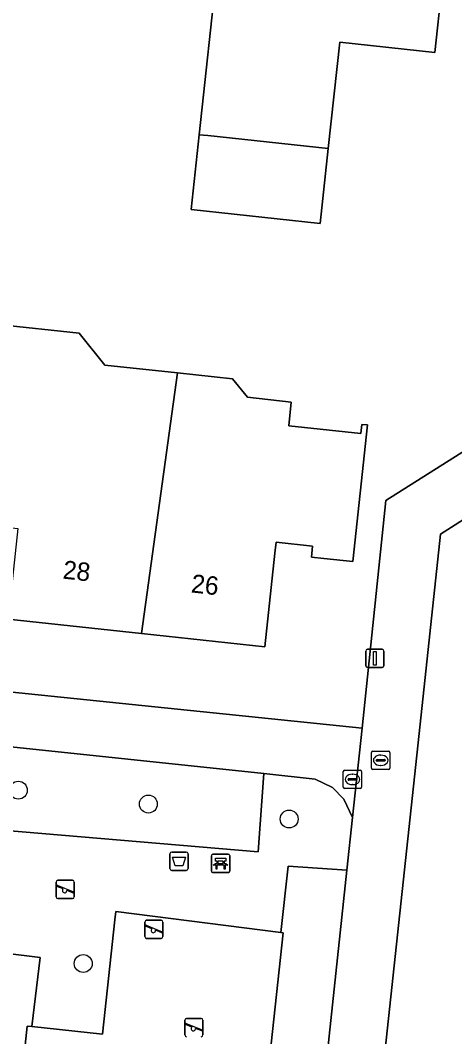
# Model space of a CAD drawing. Extents: x 162156 to 163172, y 378995 to 380779.
# Drawn here: x 162471.9 to 162495.6, y 380530.2 to 380585.7 of the extents above; entities that cross this region are included whole.
import ezdxf

# ---------------------------------------------------------------- set-up
doc = ezdxf.new("R2010")
doc.units = 0
for name, color, linetype in [('IMGEO_Afvalbak', 7, 'Continuous'), ('IMGEO_Bank', 7, 'Continuous'), ('IMGEO_Boom', 7, 'Continuous'), ('IMGEO_Erf', 7, 'Continuous'), ('IMGEO_Groenvoorziening', 7, 'Continuous'), ('IMGEO_Kolk', 7, 'Continuous'), ('IMGEO_Lichtmast', 7, 'Continuous'), ('IMGEO_Pand', 7, 'Continuous'), ('IMGEO_Pand_nummerreeks', 7, 'Continuous'), ('IMGEO_Rioolput', 7, 'Continuous'), ('IMGEO_Speelvoorziening', 7, 'Continuous'), ('IMGEO_Terreindeel_zand', 7, 'Continuous'), ('IMGEO_Voetpad_open', 7, 'Continuous')]:
    doc.layers.add(name, color=color, linetype=linetype)

msp = doc.modelspace()

# ---------------------------------------------------------------- linework, layer by layer
at = {"layer": 'IMGEO_Afvalbak'}
for p, q in [((162480.081, 380539.399), (162480.081, 380540.199)), ((162480.081, 380540.199), (162480.081, 380539.399)), ((162480.181, 380540.299), (162480.971, 380540.299)), ((162480.971, 380540.299), (162480.181, 380540.299)), ((162481.071, 380540.199), (162481.071, 380539.399)), ((162481.071, 380539.399), (162481.071, 380540.199)), ((162480.971, 380539.299), (162480.181, 380539.299)), ((162480.181, 380539.299), (162480.971, 380539.299))]:
    msp.add_line(p, q, dxfattribs=at)
msp.add_lwpolyline([(162480.224, 380540.013), (162480.928, 380540.013), (162480.779, 380539.543), (162480.373, 380539.543), (162480.224, 380540.013)], dxfattribs=at)
for centre, start, end in [((162480.181, 380540.199), 90, 180), ((162480.181, 380540.199), 90, 180), ((162480.971, 380540.199), 0, 90), ((162480.971, 380540.199), 360, 90), ((162480.181, 380539.399), 180, 270), ((162480.181, 380539.399), 180, 270), ((162480.971, 380539.399), 270, 0), ((162480.971, 380539.399), 270, 0)]:
    msp.add_arc(centre, 0.1, start, end, dxfattribs=at)
at = {"layer": 'IMGEO_Bank'}
for p, q in [((162482.342, 380539.255), (162482.342, 380540.096)), ((162482.342, 380540.096), (162482.342, 380539.255)), ((162482.417, 380540.18), (162483.258, 380540.18)), ((162483.258, 380540.18), (162482.417, 380540.18)), ((162483.342, 380540.105), (162483.342, 380539.264)), ((162483.342, 380539.264), (162483.342, 380540.105)), ((162483.039, 380539.578), (162482.646, 380539.578)), ((162482.651, 380539.686), (162482.651, 380539.792)), ((162482.695, 380539.792), (162482.695, 380539.686)), ((162482.983, 380539.798), (162482.701, 380539.798)), ((162482.701, 380539.68), (162482.983, 380539.68)), ((162482.989, 380539.686), (162482.989, 380539.792)), ((162483.033, 380539.792), (162483.033, 380539.686)), ((162483.267, 380539.18), (162482.426, 380539.18)), ((162482.426, 380539.18), (162483.267, 380539.18))]:
    msp.add_line(p, q, dxfattribs=at)
for points in [[(162482.589, 380539.578), (162482.447, 380539.578), (162482.559, 380539.68), (162482.645, 380539.68)], [(162482.645, 380539.798), (162482.559, 380539.798), (162482.559, 380539.959), (162483.122, 380539.959), (162483.122, 380539.798), (162483.039, 380539.798)], [(162482.639, 380539.571), (162482.639, 380539.364), (162482.596, 380539.364), (162482.596, 380539.571)], [(162483.039, 380539.68), (162483.122, 380539.68), (162483.234, 380539.578), (162483.095, 380539.578)], [(162483.089, 380539.571), (162483.089, 380539.364), (162483.045, 380539.364), (162483.045, 380539.571)]]:
    msp.add_lwpolyline(points, dxfattribs=at)
for centre, radius, start, end in [((162482.42, 380540.102), 0.0779, 92.4484, 184.2845), ((162482.42, 380540.102), 0.0779, 92.4484, 184.2845), ((162483.264, 380540.102), 0.0779, 2.4484, 94.2845), ((162483.264, 380540.102), 0.0779, 2.4484, 94.2845), ((162482.589, 380539.571), 0.00671, 2.8957, 87.1043), ((162482.646, 380539.571), 0.00671, 92.8957, 177.1043), ((162482.644, 380539.791), 0.00671, 2.8957, 87.1043), ((162482.644, 380539.687), 0.00671, 272.8957, 357.1043), ((162482.701, 380539.791), 0.00671, 92.8957, 177.1043), ((162482.701, 380539.687), 0.00671, 182.8957, 267.1043), ((162482.983, 380539.791), 0.00671, 2.8957, 87.1043), ((162482.983, 380539.687), 0.00671, 272.8957, 357.1043), ((162483.04, 380539.791), 0.00671, 92.8957, 177.1043), ((162483.04, 380539.687), 0.00671, 182.8957, 267.1043), ((162483.038, 380539.571), 0.00671, 2.8957, 87.1043), ((162483.095, 380539.571), 0.00671, 92.8957, 177.1043), ((162482.42, 380539.258), 0.0779, 182.4484, 274.2845), ((162482.42, 380539.258), 0.0779, 182.4484, 274.2845), ((162483.264, 380539.258), 0.0779, 272.4484, 4.2845), ((162483.264, 380539.258), 0.0779, 272.4484, 4.2845)]:
    msp.add_arc(centre, radius, start, end, dxfattribs=at)
at = {"layer": 'IMGEO_Boom'}
for centre in [(162471.814, 380543.676), (162478.904, 380542.921), (162486.581, 380542.104), (162475.353, 380534.216)]:
    msp.add_circle(centre, 0.489, dxfattribs=at)
at = {"layer": 'IMGEO_Erf'}
for points in [[(162502.189, 380600.029), (162502.472, 380602.43), (162503.344, 380607.897), (162504.412, 380614.587), (162506.479, 380624.601), (162500, 380625.199), (162474.413, 380627.947), (162438.013, 380631.313), (162439.468, 380615.71), (162440.015, 380601.307), (162439.768, 380588.845), (162437.05, 380560.078), (162436.315, 380552.915), (162465.464, 380549.639), (162490.566, 380547.063), (162491.852, 380559.491), (162500, 380564.632), (162501.13, 380565.345), (162499.992, 380567.526)], [(162470.695, 380569.092), (162475.128, 380568.614), (162476.527, 380566.876), (162480.488, 380566.449), (162483.486, 380566.126), (162484.311, 380565.121), (162486.697, 380564.863), (162486.558, 380563.571), (162490.485, 380563.147), (162490.539, 380563.644), (162490.857, 380563.61), (162490.052, 380556.153), (162488.477, 380556.323), (162487.795, 380556.397), (162487.86, 380556.996), (162485.872, 380557.211), (162485.807, 380556.611), (162485.256, 380551.504), (162478.538, 380552.228), (162471.254, 380553.014)], [(162503.119, 380562.939), (162500, 380560.947), (162494.84, 380557.651), (162493.667, 380546.763), (162491.375, 380525.475)]]:
    msp.add_lwpolyline(points, dxfattribs=at)
msp.add_lwpolyline([(162481.674, 380579.453), (162482.671, 380588.712), (162484.697, 380588.494), (162485.082, 380592.069), (162485.476, 380595.729), (162483.408, 380595.952), (162484.419, 380605.366), (162484.765, 380605.338), (162484.995, 380608.169), (162490.766, 380607.701), (162490.528, 380604.766), (162491.55, 380604.656), (162490.887, 380598.495), (162496.039, 380597.94), (162495.295, 380591.027), (162494.532, 380583.945), (162489.336, 380584.504), (162488.71, 380578.696), (162488.27, 380574.611), (162481.234, 380575.368)], close=True, dxfattribs=at)
at = {"layer": 'IMGEO_Groenvoorziening'}
for points in [[(162469.868, 380541.578), (162484.897, 380540.319), (162485.2, 380544.58), (162470.351, 380546.161)], [(162486.523, 380539.523), (162489.731, 380539.305), (162490.036, 380542.183), (162489.57, 380543.192), (162488.951, 380543.816), (162488.005, 380544.281), (162485.2, 380544.58), (162484.897, 380540.319), (162469.868, 380541.578), (162469.175, 380535.01), (162473.002, 380534.554), (162472.559, 380530.774), (162476.412, 380530.364), (162477.075, 380536.599), (162477.123, 380537.052), (162486.125, 380535.903)], [(162489.731, 380539.305), (162486.523, 380539.523), (162486.125, 380535.903), (162486.251, 380535.887), (162485.391, 380527.81), (162485.237, 380527.826), (162482.178, 380500), (162481.589, 380494.65), (162484.947, 380494.337), (162485.141, 380496.162), (162485.549, 380500)], [(162467.353, 380486.346), (162468.953, 380500), (162471.523, 380521.934), (162469.762, 380522.121), (162469.984, 380524.21), (162471.585, 380524.04), (162472.305, 380530.801), (162472.559, 380530.774), (162473.002, 380534.554), (162469.175, 380535.01), (162469.055, 380533.871), (162467.978, 380524.494), (162467.276, 380517.746), (162465.46, 380500), (162464.077, 380486.7)]]:
    msp.add_lwpolyline(points, close=True, dxfattribs=at)
at = {"layer": 'IMGEO_Kolk'}
for p, q in [((162489.533, 380543.84), (162489.533, 380544.692)), ((162489.608, 380544.766), (162490.46, 380544.766)), ((162490.021, 380544.546), (162490.046, 380544.546)), ((162490.534, 380544.692), (162490.534, 380543.84)), ((162489.792, 380544.26), (162489.792, 380544.272)), ((162490.23, 380544.223), (162489.832, 380544.223)), ((162489.835, 380544.309), (162490.233, 380544.309)), ((162490.044, 380543.986), (162490.019, 380543.986)), ((162490.276, 380544.272), (162490.276, 380544.26)), ((162490.46, 380543.766), (162489.608, 380543.766))]:
    msp.add_line(p, q, dxfattribs=at)
for points in [[(162489.533, 380543.84), (162489.533, 380544.692)], [(162489.608, 380544.766), (162490.46, 380544.766)], [(162490.534, 380544.692), (162490.534, 380543.84)], [(162490.46, 380543.766), (162489.608, 380543.766)]]:
    msp.add_lwpolyline(points, dxfattribs=at)
for centre, radius, start, end in [((162489.61, 380544.69), 0.0765, 91.552, 178.448), ((162489.61, 380544.69), 0.0765, 91.552, 178.448), ((162490.458, 380544.69), 0.0765, 1.552, 88.448), ((162490.458, 380544.69), 0.0765, 1.552, 88.448), ((162489.832, 380544.269), 0.0403, 85.8775, 175.7526), ((162489.829, 380544.259), 0.0366, 178.938, 274.7102), ((162490.233, 380544.266), 0.043, 264.8664, 352.4533), ((162490.237, 380544.271), 0.0386, 1.7309, 96.639), ((162489.61, 380543.842), 0.0765, 181.552, 268.448), ((162489.61, 380543.842), 0.0765, 181.552, 268.448), ((162490.458, 380543.842), 0.0765, 271.552, 358.448), ((162490.458, 380543.842), 0.0765, 271.552, 358.448)]:
    msp.add_arc(centre, radius, start, end, dxfattribs=at)
for centre, major_axis, ratio, start_param, end_param in [((162490.02, 380544.266), (-0.387, 0.002), 0.722429, 4.712389, 7.853982), ((162490.045, 380544.266), (-0.39, 0.002), 0.717154, 1.570796, 4.712389)]:
    msp.add_ellipse(centre, major_axis=major_axis, ratio=ratio, start_param=start_param, end_param=end_param, dxfattribs=at)
at = {"layer": 'IMGEO_Lichtmast'}
for p, q in [((162490.757, 380550.473), (162490.757, 380551.273)), ((162490.757, 380551.273), (162490.757, 380550.473)), ((162490.857, 380551.373), (162491.647, 380551.373)), ((162491.647, 380551.373), (162490.857, 380551.373)), ((162491.747, 380551.273), (162491.747, 380550.473)), ((162491.747, 380550.473), (162491.747, 380551.273)), ((162491.647, 380550.373), (162490.857, 380550.373)), ((162490.857, 380550.373), (162491.647, 380550.373))]:
    msp.add_line(p, q, dxfattribs=at)
msp.add_lwpolyline([(162491.177, 380551.248), (162491.327, 380551.248), (162491.327, 380550.498), (162491.177, 380550.498), (162491.177, 380551.248)], dxfattribs=at)
for centre, start, end in [((162490.857, 380551.273), 90, 180), ((162490.857, 380551.273), 90, 180), ((162491.647, 380551.273), 0, 90), ((162491.647, 380551.273), 360, 90), ((162490.857, 380550.473), 180, 270), ((162490.857, 380550.473), 180, 270), ((162491.647, 380550.473), 270, 0), ((162491.647, 380550.473), 270, 0)]:
    msp.add_arc(centre, 0.1, start, end, dxfattribs=at)
at = {"layer": 'IMGEO_Pand'}
for points in [[(162488.71, 380578.696), (162489.336, 380584.504), (162494.532, 380583.945), (162495.295, 380591.027), (162485.082, 380592.069), (162484.697, 380588.494), (162482.671, 380588.712), (162481.674, 380579.453), (162482.144, 380579.402)], [(162488.71, 380578.696), (162482.144, 380579.402), (162481.674, 380579.453), (162481.234, 380575.368), (162488.27, 380574.611)], [(162478.538, 380552.228), (162480.488, 380566.449), (162476.527, 380566.876), (162475.128, 380568.614), (162470.695, 380569.092), (162468.878, 380567.629), (162468.642, 380565.441), (162467.658, 380565.547), (162466.753, 380565.645), (162466.045, 380558.576), (162471.787, 380557.957), (162471.254, 380553.014)], [(162478.538, 380552.228), (162485.256, 380551.504), (162485.807, 380556.611), (162485.872, 380557.211), (162487.86, 380556.996), (162487.795, 380556.397), (162488.477, 380556.323), (162490.052, 380556.153), (162490.857, 380563.61), (162490.539, 380563.644), (162490.485, 380563.147), (162486.558, 380563.571), (162486.697, 380564.863), (162484.311, 380565.121), (162483.486, 380566.126), (162480.488, 380566.449)]]:
    msp.add_lwpolyline(points, close=True, dxfattribs=at)
at = {"layer": 'IMGEO_Rioolput'}
for p, q in [((162491.076, 380544.884), (162491.076, 380545.736)), ((162491.151, 380545.81), (162492.003, 380545.81)), ((162492.077, 380545.736), (162492.077, 380544.884)), ((162491.335, 380545.304), (162491.335, 380545.316)), ((162491.773, 380545.267), (162491.375, 380545.267)), ((162491.378, 380545.353), (162491.776, 380545.353)), ((162491.564, 380545.59), (162491.589, 380545.59)), ((162491.819, 380545.316), (162491.819, 380545.304)), ((162492.003, 380544.81), (162491.151, 380544.81)), ((162491.587, 380545.03), (162491.562, 380545.03))]:
    msp.add_line(p, q, dxfattribs=at)
for points in [[(162491.076, 380544.884), (162491.076, 380545.736)], [(162491.151, 380545.81), (162492.003, 380545.81)], [(162492.077, 380545.736), (162492.077, 380544.884)], [(162492.003, 380544.81), (162491.151, 380544.81)]]:
    msp.add_lwpolyline(points, dxfattribs=at)
for centre, radius, start, end in [((162491.153, 380545.734), 0.0765, 91.552, 178.448), ((162491.153, 380545.734), 0.0765, 91.552, 178.448), ((162492.001, 380545.734), 0.0765, 1.552, 88.448), ((162492.001, 380545.734), 0.0765, 1.552, 88.448), ((162491.375, 380545.313), 0.0403, 85.8775, 175.7526), ((162491.372, 380545.303), 0.0366, 178.938, 274.7102), ((162491.776, 380545.31), 0.043, 264.8664, 352.4533), ((162491.78, 380545.315), 0.0386, 1.7309, 96.639), ((162491.153, 380544.886), 0.0765, 181.552, 268.448), ((162491.153, 380544.886), 0.0765, 181.552, 268.448), ((162492.001, 380544.886), 0.0765, 271.552, 358.448), ((162492.001, 380544.886), 0.0765, 271.552, 358.448)]:
    msp.add_arc(centre, radius, start, end, dxfattribs=at)
for centre, major_axis, ratio, start_param, end_param in [((162491.563, 380545.31), (-0.387, 0.002), 0.722429, 4.712389, 7.853982), ((162491.588, 380545.31), (-0.39, 0.002), 0.717154, 1.570796, 4.712389)]:
    msp.add_ellipse(centre, major_axis=major_axis, ratio=ratio, start_param=start_param, end_param=end_param, dxfattribs=at)
at = {"layer": 'IMGEO_Speelvoorziening'}
for p, q in [((162473.871, 380537.86), (162473.871, 380538.66)), ((162473.871, 380538.66), (162473.871, 380537.86)), ((162474.254, 380538.288), (162473.915, 380538.425)), ((162473.94, 380538.485), (162474.816, 380538.132)), ((162473.971, 380538.76), (162474.761, 380538.76)), ((162474.761, 380538.76), (162473.971, 380538.76)), ((162474.861, 380538.66), (162474.861, 380537.86)), ((162474.861, 380537.86), (162474.861, 380538.66)), ((162474.792, 380538.072), (162474.452, 380538.209)), ((162474.761, 380537.76), (162473.971, 380537.76)), ((162473.971, 380537.76), (162474.761, 380537.76)), ((162478.711, 380535.683), (162478.711, 380536.483)), ((162478.711, 380536.483), (162478.711, 380535.683)), ((162479.094, 380536.111), (162478.755, 380536.248)), ((162478.78, 380536.308), (162479.656, 380535.955)), ((162478.811, 380536.583), (162479.601, 380536.583)), ((162479.601, 380536.583), (162478.811, 380536.583)), ((162479.701, 380536.483), (162479.701, 380535.683)), ((162479.701, 380535.683), (162479.701, 380536.483)), ((162479.632, 380535.895), (162479.292, 380536.032)), ((162479.601, 380535.583), (162478.811, 380535.583)), ((162478.811, 380535.583), (162479.601, 380535.583)), ((162480.993, 380531.224), (162481.783, 380531.224)), ((162481.783, 380531.224), (162480.993, 380531.224)), ((162480.893, 380530.324), (162480.893, 380531.124)), ((162480.893, 380531.124), (162480.893, 380530.324)), ((162481.276, 380530.752), (162480.937, 380530.889)), ((162480.962, 380530.949), (162481.838, 380530.596)), ((162481.814, 380530.536), (162481.474, 380530.673)), ((162481.883, 380531.124), (162481.883, 380530.324)), ((162481.883, 380530.324), (162481.883, 380531.124))]:
    msp.add_line(p, q, dxfattribs=at)
for centre, radius, start, end in [((162473.971, 380538.66), 0.1, 90, 180), ((162473.971, 380538.66), 0.1, 90, 180), ((162473.928, 380538.455), 0.0327, 68.078, 248.078), ((162474.761, 380538.66), 0.1, 0, 90), ((162474.761, 380538.66), 0.1, 360, 90), ((162473.971, 380537.86), 0.1, 180, 270), ((162473.971, 380537.86), 0.1, 180, 270), ((162474.333, 380538.198), 0.12, 130.9928, 5.1632), ((162474.761, 380537.86), 0.1, 270, 0), ((162474.761, 380537.86), 0.1, 270, 0), ((162474.804, 380538.102), 0.0327, 248.078, 68.078), ((162478.811, 380536.483), 0.1, 90, 180), ((162478.811, 380536.483), 0.1, 90, 180), ((162478.768, 380536.278), 0.0327, 68.078, 248.078), ((162479.601, 380536.483), 0.1, 0, 90), ((162479.601, 380536.483), 0.1, 360, 90), ((162478.811, 380535.683), 0.1, 180, 270), ((162478.811, 380535.683), 0.1, 180, 270), ((162479.173, 380536.021), 0.12, 130.9928, 5.1632), ((162479.601, 380535.683), 0.1, 270, 0), ((162479.601, 380535.683), 0.1, 270, 0), ((162479.644, 380535.925), 0.0327, 248.078, 68.078), ((162480.993, 380531.124), 0.1, 90, 180), ((162480.993, 380531.124), 0.1, 90, 180), ((162481.783, 380531.124), 0.1, 0, 90), ((162481.783, 380531.124), 0.1, 360, 90), ((162480.95, 380530.919), 0.0327, 68.078, 248.078), ((162481.355, 380530.662), 0.12, 130.9928, 5.1632), ((162480.993, 380530.324), 0.1, 180, 270), ((162480.993, 380530.324), 0.1, 180, 270), ((162481.783, 380530.324), 0.1, 270, 0), ((162481.783, 380530.324), 0.1, 270, 0), ((162481.826, 380530.566), 0.0327, 248.078, 68.078)]:
    msp.add_arc(centre, radius, start, end, dxfattribs=at)
at = {"layer": 'IMGEO_Terreindeel_zand'}
msp.add_lwpolyline([(162486.251, 380535.887), (162486.125, 380535.903), (162477.123, 380537.052), (162477.075, 380536.599), (162476.412, 380530.364), (162472.559, 380530.774), (162472.305, 380530.801), (162471.585, 380524.04), (162469.984, 380524.21), (162469.762, 380522.121), (162471.523, 380521.934), (162478.353, 380521.207), (162478.575, 380523.296), (162484.306, 380527.925), (162485.237, 380527.826), (162485.391, 380527.81)], close=True, dxfattribs=at)
at = {"layer": 'IMGEO_Voetpad_open'}
for points in [[(162501.46, 380565.557), (162501.13, 380565.345), (162500, 380564.632), (162491.852, 380559.491), (162490.566, 380547.063), (162490.036, 380542.183), (162489.731, 380539.305), (162485.549, 380500), (162485.141, 380496.162), (162487.858, 380495.873), (162488.29, 380500), (162488.985, 380506.63), (162489.359, 380506.6), (162490.197, 380514.538)], [(162490.197, 380514.538), (162491.375, 380525.475), (162493.667, 380546.763), (162494.84, 380557.651), (162500, 380560.947), (162503.119, 380562.939), (162503.477, 380563.168)]]:
    msp.add_lwpolyline(points, dxfattribs=at)
msp.add_lwpolyline([(162469.868, 380541.578), (162470.351, 380546.161), (162485.2, 380544.58), (162488.005, 380544.281), (162488.951, 380543.816), (162489.57, 380543.192), (162490.036, 380542.183), (162490.566, 380547.063), (162465.464, 380549.639), (162436.315, 380552.915), (162432.449, 380545.496), (162431.721, 380537.758), (162469.055, 380533.871), (162469.175, 380535.01)], close=True, dxfattribs=at)

# ---------------------------------------------------------------- texts
at = {"layer": 'IMGEO_Pand_nummerreeks'}
for s, p in [('28', (162474.206, 380555.23)), ('26', (162481.204, 380554.475))]:
    msp.add_text(s, height=1, rotation=353.8449, dxfattribs=at).set_placement(p)

doc.saveas('drawing.dxf')
